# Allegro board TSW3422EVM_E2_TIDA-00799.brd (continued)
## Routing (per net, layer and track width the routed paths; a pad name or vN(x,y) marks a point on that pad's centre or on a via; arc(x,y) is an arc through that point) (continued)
P4.7V:
  vias: v1(33.71,40.51) v1(33.83,42.16) v1(33.83,41.28) v1(34.21,39.88) v1(35.1,39.88) v1(35.74,42.29) v1(35.74,41.28) v1(35.74,40.26) v1(35.74,39.37) v1(36.63,39.62) v1(36.88,40.39)
VIN-: length 7.2
  TOP w0.483: R16.1 R28.1 33.84,90.81 32.91,90.81 U1.2
A_INM: length 16.1
  TOP w0.483: J2.1 3.78,72.98 9.17,67.59 R9.1
A_INP: length 16.1
  TOP w0.483: R4.1 9.23,62.51 3.81,57.1 J1.1
AI_NM: length 4.6
  TOP w0.483: T2.4 T1.6
AI_NP: length 4.6
  TOP w0.483: T2.6 T1.4
AIN+: length 3
  TOP w0.483: C1.1 38.68,62.51 T2.1
AIN-: length 3.1
  TOP w0.483: T2.3 38.66,67.59 C7.1
AINM: length 3.2
  TOP w0.216: U5.8 65.51,64.77 65.57,64.83 67.11,64.83 67.5,64.44 R91.2
AINM_M: length 4.3
  TOP w0.483: R14.1 R10.2 R13.2 L3.1
AINMM_M: length 4.5
  TOP w0.483: R14.2 R11.2 48.82,67.67 49.4,67.09 49.4,65.67 R15.1
AINP: length 3.2
  TOP w0.216: U5.9 65.51,65.27 65.57,65.2 67.51,65.2 R50.2
AINP_P: length 4.3
  TOP w0.483: L1.1 R1.2 R6.1 R2.1
AINPP_P: length 4.3
  TOP w0.483: R3.1 49.43,63.12 48.77,62.46 R5.1 R2.2
B+: length 1.2
  TOP w0.254: R20.1 46.47,75.3 U2.10
B-: length 1.2
  TOP w0.254: U2.11 46.85,75.63 R33.1
B_INM: length 36.7
  TOP w0.483: R42.1 R44.1 R41.1 81,82.71 81,83.25 82.77,85.02 82.77,92.1 J5.1
B_INP: length 36.7
  TOP w0.483: R40.1 R38.1 81.75,80.93 82.29,80.93 84.66,83.3 91.75,83.3 J4.1
BI_NM: length 2.4
  TOP w0.483: R43.2 72.4,72.03 C20.2 72.31,71.64 L7.1
BI_NP: length 2.4
  TOP w0.483: R39.2 71.59,72.84 C20.1 71.2,72.75 L6.1
BIN+: length 7.1
  TOP w0.254: 76.62,75.79 U3.4 76.97,75.07
  TOP w0.483: 76.62,75.79 D2.3 R40.2 ; 76.97,75.07 77.35,74.7 R36.1 77.35,74.36 C101.2
BIN-: length 7.1
  TOP w0.254: 74.63,77.42 U3.6 75.35,77.06
  TOP w0.483: C100.2 R37.1 74.26,77.79 74.63,77.42 ; 75.35,77.06 D6.3 78.19,79.9
BIN_+: length 4.7
  TOP w0.254: 73.93,75.64 U3.9 73.57,76.36
  TOP w0.483: R39.1 73.07,74.78 73.93,75.64 ; C100.1 R37.2 73.2,76.73 73.57,76.36
BIN_-: length 4.8
  TOP w0.254: 75.21,74.36 75.37,74.53 U3.1 75.38,74.55 75.91,74.01
  TOP w0.483: R43.1 74.36,73.51 75.21,74.36 ; 75.91,74.01 76.29,73.64 R36.2 C101.1
BINM: length 3.2
  TOP w0.216: R23.2 67.13,67.87 67.13,67.56 66.69,67.12 66.37,67.12 66.33,67.17 65.23,67.17 65.13,67.27 U5.13
BINP: length 3.2
  TOP w0.216: U5.12 64.96,66.77 65,66.8 66.17,66.8 66.3,66.67 67.13,66.67 67.68,67.23 R26.2
C_INM: length 36.7
  TOP w0.483: J7.1 96.09,71.29 91.08,66.28 87.95,66.28 87.93,66.27 87.82,66.27 R92.1 R54.1 R52.1
C_INP: length 36.7
  TOP w0.483: R51.1 R48.1 87.46,64.11 87.84,63.73 91.2,63.73 96.22,58.72 J6.1
CI_NM: length 2.4
  TOP w0.483: R53.2 74.56,64.44 C25.2 74.22,64.22 L9.1
CI_NP: length 2.4
  TOP w0.483: R49.2 74.56,65.58 C25.1 74.22,65.8 L8.1
CIN+: length 7.1
  TOP w0.254: 80.2,64.11 U4.4 79.95,63.35
  TOP w0.483: C102.2 79.7,61.39 R46.1 79.95,62.82 79.95,63.35 ; R51.2 D3.3 80.2,64.11
CIN-: length 7.1
  TOP w0.254: 79.95,66.66 U4.6 80.2,65.9
  TOP w0.483: 80.2,65.9 D7.3 R52.2 ; 79.95,66.66 79.95,67.19 R47.1 C99.2
CIN_+: length 4.7
  TOP w0.254: 78.19,65.9 U4.9 78.45,66.66
  TOP w0.483: 78.19,65.9 76.98,65.9 R49.1 ; 78.45,66.66 78.45,67.19 R47.2 C99.1
CIN_-: length 4.7
  TOP w0.254: 78.45,63.35 U4.1 78.19,64.11
  TOP w0.483: 78.19,64.11 76.98,64.11 R53.1 ; C102.1 78.69,61.39 R46.2 78.45,62.82 78.45,63.35
CINM: length 6
  TOP w0.254: U5.30 56.35,67.27 56.3,67.22 56.02,67.22 55.55,67.69 54.66,67.69 54.41,67.95 54.41,68.45 54.15,68.71 53.64,68.71 52.94,69.41 R34.2
CINP: length 6
  TOP w0.254: R21.2 52.61,69.16 53.99,67.78 54.49,67.28 55.38,67.28 55.85,66.81 56.3,66.81 56.35,66.77 U5.31
CLK_INP: length 2.2
  TOP w0.483: T3.1 C49.1
CLKINM: length 12.9
  TOP w0.216: U5.22 60.71,69.37 60.78,69.44 60.78,70.33 62.51,72.06 62.51,72.67 62.26,72.92 61.75,72.92 R61.1
  TOP w0.483: 60.99,79.12 60.99,77.24 60.38,76.63 60.38,75.31 60.99,74.7 60.99,73.69 R61.1
CLKINP: length 12.9
  TOP w0.216: U5.21 61.21,69.37 61.14,69.44 61.14,70.17 63.17,72.2 63.17,72.71 63.39,72.92 63.58,72.92 R60.2
  TOP w0.483: 66.07,79.12 66.07,75.41 R60.2
CLOCK_IN: length 8.5
  TOP w0.483: C49.2 J8.1
D_INP: length 9.6
  TOP w0.483: J3.1 JP1.1 R32.2 R22.1
DA0M: length 57
  TOP w0.216: U5.4 65.82,62.77 65.88,62.7 67.08,62.7 70.42,59.36 70.42,52.06 70.18,51.82 70.18,50.33 70.47,50.04 70.47,10.67 70.5,10.64 J12.32
DA0P: length 56.9
  TOP w0.216: U5.3 65.82,62.27 65.88,62.33 66.93,62.33 67.39,61.87 67.39,61.65 67.39,61.44 67.54,61.29 67.76,61.29 67.97,61.29 68.9,60.36 68.9,60.01 69.09,59.82 69.44,59.82 70.05,59.21 70.05,52.21 69.74,51.89 69.74,50.25 70.1,49.89 70.1,10.7 69.99,10.6 J12.34
DA1M: length 57
  TOP w0.216: U5.2 65.82,61.77 65.88,61.7 66.25,61.7 68.2,59.75 68.2,52.51 68.2,52.21 67.51,51.52 67.51,50.29 68.2,49.6 68.2,49.3 68.2,48.35 67.37,47.52 67.37,46.57 68.2,45.74 68.2,44.49 67.37,43.66 67.37,42.71 68.2,41.88 68.2,40.63 67.73,40.16 67.73,38.49 68.2,38.02 68.2,14.78 68.95,14.03 68.95,13.84 68.97,13.83 68.97,10.63 68.99,10.6 J12.38
DA1P: length 57
  TOP w0.216: J12.40 68.49,10.6 68.6,10.7 68.6,13.68 68.59,13.69 68.59,13.87 67.84,14.63 67.84,37.86 67.36,38.34 67.36,40.31 67.83,40.78 67.83,41.73 67.01,42.56 67.01,43.81 67.83,44.64 67.83,45.59 67.01,46.42 67.01,47.67 67.83,48.5 67.83,49.45 67.14,50.14 67.14,51.67 67.83,52.36 67.83,59.6 67.05,60.38 66.83,60.38 66.72,60.27 66.5,60.27 66.35,60.42 66.35,60.64 66.47,60.75 66.47,60.96 66.1,61.33 65.88,61.33 65.82,61.27 U5.1
DAVP: length 4.6
  TOP w0.483: 26.73,95.19 D1.3 R22.2
DB0M: length 56.9
  TOP w0.216: J12.44 67.49,10.67 67.46,10.7 67.46,13.23 66.24,14.45 66.24,29.54 65.34,30.44 65.34,31.39 66.24,32.29 66.24,33.55 65.34,34.45 65.34,35.4 66.24,36.31 66.24,37.56 65.34,38.46 65.34,39.42 66.24,40.32 66.24,41.58 65.34,42.48 65.34,43.43 66.24,44.33 66.24,45.59 65.34,46.49 65.34,47.44 66.24,48.35 66.24,49.6 65.34,50.5 65.34,51.46 66.24,52.36 66.24,56.43 64.14,58.53 64.14,59.59 64.21,59.66 U5.56
DB0P: length 57
  TOP w0.216: J12.46 66.99,10.6 67.1,10.7 67.1,13.08 65.87,14.3 65.87,29.38 64.97,30.29 64.97,31.54 65.87,32.44 65.87,33.4 64.97,34.3 64.97,35.56 65.87,36.46 65.87,37.41 64.97,38.31 64.97,39.57 65.87,40.47 65.87,41.42 64.97,42.33 64.97,43.58 65.87,44.48 65.87,45.44 64.97,46.34 64.97,47.6 65.87,48.5 65.87,49.45 64.97,50.35 64.97,51.61 65.87,52.51 65.87,56.27 63.78,58.37 63.78,59.59 63.71,59.66 U5.55
DB1M: length 56.9
  TOP w0.216: U5.54 63.21,59.66 63.14,59.59 63.14,56.86 64.21,55.79 64.21,52.32 63.27,51.38 63.27,50.43 64.21,49.49 64.21,48.23 63.27,47.29 63.27,46.34 64.21,45.4 64.21,44.14 63.27,43.2 63.27,42.25 64.21,41.31 64.21,40.05 63.27,39.11 63.27,38.16 64.21,37.22 64.21,35.96 63.27,35.02 63.27,34.07 64.21,33.13 64.21,31.87 63.27,30.93 63.27,29.98 64.21,29.04 64.21,14.25 65.96,12.5 65.96,10.7 65.99,10.67 J12.50
DB1P: length 57
  TOP w0.216: J12.52 65.49,10.6 65.6,10.7 65.6,12.34 63.84,14.1 63.84,28.89 62.9,29.83 62.9,31.09 63.84,32.03 63.84,32.98 62.9,33.92 62.9,35.18 63.84,36.12 63.84,37.07 62.9,38.01 62.9,39.27 63.84,40.21 63.84,41.16 62.9,42.1 62.9,43.35 63.84,44.29 63.84,45.25 62.9,46.19 62.9,47.44 63.84,48.38 63.84,49.34 62.9,50.28 62.9,51.53 63.84,52.47 63.84,55.64 62.78,56.71 62.78,59.59 62.71,59.66 U5.53
DBIN+: length 1
  TOP w0.483: L4.1 R20.2
DBIN-: length 1
  TOP w0.483: L5.1 R33.2
DBIN_M: length 3.6
  TOP w0.483: L5.2 51.32,71.86 51.32,71.5 52.04,70.78 R34.1
DBIN_P: length 3.6
  TOP w0.483: L4.2 R25.2 50.24,70.78 C12.1 51.32,70.06 R21.1
DC0M: length 56.9
  TOP w0.216: U5.46 59.21,59.66 59.14,59.59 59.14,57.26 57.75,55.87 57.75,54.54 58.65,53.64 58.65,52.38 57.75,51.48 57.75,50.53 58.65,49.63 58.65,48.37 57.75,47.47 57.75,46.52 58.65,45.62 58.65,44.36 57.75,43.46 57.75,42.5 58.65,41.6 58.65,40.34 57.75,39.44 57.75,38.49 58.65,37.59 58.65,36.33 57.75,35.43 57.75,34.48 58.65,33.58 58.65,32.32 57.75,31.42 57.75,13.64 56,11.89 J12.70
DC0P: length 56.9
  TOP w0.216: J12.72 55.5,11.91 57.38,13.79 57.38,31.57 58.28,32.47 58.28,33.42 57.38,34.32 57.38,35.58 58.28,36.48 58.28,37.44 57.38,38.34 57.38,39.6 58.28,40.5 58.28,41.45 57.38,42.35 57.38,43.61 58.28,44.51 58.28,45.46 57.38,46.36 57.38,47.62 58.28,48.52 58.28,49.48 57.38,50.38 57.38,51.64 58.28,52.54 58.28,53.49 57.38,54.39 57.38,56.02 58.78,57.42 58.78,59.59 58.71,59.66 U5.45
DC1M: length 57
  TOP w0.216: U5.44 58.21,59.66 58.14,59.59 58.14,58.7 56.12,56.68 56.12,54.14 56.85,53.42 56.85,52.16 55.94,51.26 55.94,50.3 56.85,49.4 56.85,48.15 55.94,47.24 55.94,46.29 56.85,45.39 56.85,44.13 55.94,43.23 55.94,42.28 56.85,41.38 56.85,40.12 55.94,39.22 55.94,38.26 56.85,37.36 56.85,36.11 55.94,35.2 55.94,34.25 56.85,33.35 56.85,32.09 55.94,31.19 55.94,14.36 54.4,12.82 54.4,11.81 54.5,11.72 J12.76
DC1P: length 57
  TOP w0.216: U5.43 57.71,59.66 57.78,59.59 57.78,58.86 55.75,56.83 55.75,53.99 56.48,53.26 56.48,52.31 55.58,51.41 55.58,50.15 56.48,49.25 56.48,48.3 55.58,47.4 55.58,46.14 56.48,45.24 56.48,44.28 55.58,43.38 55.58,42.13 56.48,41.22 56.48,40.27 55.58,39.37 55.58,38.11 56.48,37.21 56.48,36.26 55.58,35.36 55.58,34.1 56.48,33.2 56.48,32.25 55.58,31.34 55.58,14.52 54,12.94 J12.78
DCLKM: length 56.9
  TOP w0.216: U5.51 61.71,59.66 61.64,59.59 61.64,54.87 62.52,53.99 62.52,52.32 61.43,51.23 61.43,50.28 62.33,49.38 62.33,48.12 61.43,47.22 61.43,46.27 62.33,45.36 62.33,44.11 61.43,43.2 61.43,42.25 62.33,41.35 62.33,40.09 61.43,39.19 61.43,38.24 62.33,37.34 62.33,36.08 61.43,35.18 61.43,34.23 62.33,33.32 62.33,32.07 61.43,31.16 61.43,30.21 62.33,29.31 62.33,13.63 64.49,11.47 J12.56
DCLKP: length 56.8
  TOP w0.216: J12.58 63.99,11.37 61.96,13.4 61.96,29.16 61.06,30.06 61.06,31.32 61.96,32.22 61.96,33.17 61.06,34.07 61.06,35.33 61.96,36.23 61.96,37.18 61.06,38.09 61.06,39.34 61.96,40.25 61.96,41.2 61.06,42.1 61.06,43.36 61.96,44.26 61.96,45.21 61.06,46.11 61.06,47.37 61.96,48.27 61.96,49.22 61.06,50.13 61.06,51.38 62.15,52.48 62.15,53.84 61.28,54.71 61.28,59.59 61.21,59.66 U5.50
DD0M: length 56.9
  TOP w0.216: U5.42 56.1,61.27 56.04,61.33 55.53,61.33 55.18,60.99 55.18,60.77 55.26,60.69 55.26,60.47 55.11,60.32 54.9,60.32 54.81,60.4 54.6,60.4 53.76,59.56 53.76,54.17 54.64,53.29 54.64,52.03 53.76,51.16 53.76,50.2 54.64,49.33 54.64,48.07 53.99,47.42 53.99,46.01 54.64,45.37 54.64,44.11 53.76,43.23 53.76,14.6 52.9,13.75 52.9,10.55 53.03,10.41 J12.82
DD0P: length 57
  TOP w0.216: U5.41 56.1,61.77 56.04,61.7 55.38,61.7 53.39,59.72 53.39,54.01 54.27,53.14 54.27,52.19 53.39,51.31 53.39,50.05 54.27,49.18 54.27,48.22 53.62,47.58 53.62,45.86 54.27,45.21 54.27,44.26 53.39,43.38 53.39,14.76 52.53,13.9 J12.84
DD1M: length 57
  TOP w0.216: U5.40 56.1,62.27 56.04,62.33 54.8,62.33 54.51,62.04 54.51,61.64 54.33,61.47 53.94,61.47 53.02,60.56 53.02,60.34 53.04,60.32 53.04,60.11 52.89,59.95 52.68,59.95 52.66,59.97 52.44,59.97 51.47,59 51.47,9.58 J12.88
DD1P: length 57.1
  TOP w0.216: J12.90 51.1,9.67 51.1,59.16 54.65,62.7 56.04,62.7 56.1,62.77 U5.39
DIN_P: length 3.2
  TOP w0.483: R89.2 C11.1 U1.3
DINM: length 6.8
  TOP w0.216: U5.35 56.41,64.77 56.35,64.83 50.88,64.83 R3.2
DINP: length 6.8
  TOP w0.216: U5.34 56.41,65.27 56.35,65.2 50.88,65.2 R15.2
FCLKM: length 56.9
  TOP w0.216: J12.64 57.5,10.52 57.4,10.61 57.4,11.25 59.7,13.55 59.7,31.12 60.6,32.02 60.6,33.27 59.7,34.18 59.7,35.13 60.6,36.03 60.6,37.29 59.7,38.19 59.7,39.14 60.6,40.04 60.6,41.3 59.7,42.2 59.7,43.15 60.6,44.06 60.6,45.31 59.7,46.22 59.7,47.17 60.6,48.07 60.6,49.33 59.7,50.23 59.7,51.18 60.6,52.08 60.6,53.34 59.7,54.24 59.7,55.93 60.64,56.87 60.64,59.59 60.71,59.66 U5.49
FCLKP: length 56.9
  TOP w0.216: U5.48 60.21,59.66 60.28,59.59 60.28,57.02 59.33,56.08 59.33,54.09 60.24,53.19 60.24,52.24 59.33,51.33 59.33,50.08 60.24,49.17 60.24,48.22 59.33,47.32 59.33,46.06 60.24,45.16 60.24,44.21 59.33,43.31 59.33,42.05 60.24,41.15 60.24,40.2 59.33,39.29 59.33,38.04 60.24,37.14 60.24,36.18 59.33,35.28 59.33,34.02 60.24,33.12 60.24,32.17 59.33,31.27 59.33,13.7 57,11.37 J12.66
FPGA_CSEL: length 67.1
  TOP w0.203: J12.115 v1(44.5,4.6)
  TOP w0.254: R70.1 v1(102.67,20.96)
  BOTTOM w0.203: v1(102.67,20.96) 91.01,9.3 49.68,9.3 47.04,6.65 47.04,6.07 45.59,4.62 44.53,4.62 v1(44.5,4.6)
FPGA_SCLK: length 62.9
  TOP w0.203: J12.119 43.49,3.93 43.18,4.24 v1(43.18,4.85)
  TOP w0.254: R67.1 v1(95.81,20.96)
  BOTTOM w0.203: v1(95.81,20.96) 87.12,12.27 48.21,12.27 46.79,10.85 46.79,9.4 44.02,6.63 44.02,6.07 43.18,5.23 v1(43.18,4.85)
FPGA_SDI: length 65.9
  TOP w0.203: J12.117 v1(43.99,5.18)
  TOP w0.254: R68.1 v1(100.38,20.96)
  BOTTOM w0.203: v1(43.99,5.18) 45.21,5.18 46,5.97 46,6.83 49.16,9.99 89.42,9.99 v1(100.38,20.96)
FPGA_SDO: length 63.5
  TOP w0.203: J12.113 v1(45.01,5.82)
  TOP w0.254: R69.1 v1(98.09,20.96)
  BOTTOM w0.203: v1(45.01,5.82) 44.91,5.92 44.91,6.76 48.29,10.13 48.29,10.85 49.03,11.59 88.73,11.59 v1(98.09,20.96)
FTDI_VCCIO1.8V: length 92.9
  TOP w0.483: U6.4 v1(100.26,27.29) ; FB6.1 v1(25.07,44.6)
  LYR3_PWR w0.483: v1(100.26,27.29) 100.26,28.58 99.38,29.46 97.08,29.46 89.46,37.08 65.96,37.08 65.58,37.47 62.28,37.47 61.9,37.85 49.94,37.85 48.92,38.86 45.06,38.86 44.88,38.68 42.95,38.68 42.37,38.1 40.26,38.1 38,35.84 36.68,35.84 35.94,36.09 33.86,36.09 33.32,36.63 27.51,36.63 27.05,37.08 27.05,38.58 23.52,42.11 23.52,43.05 v1(25.07,44.6)
IN+: length 9.4
  TOP w0.305: C13.2 43.72,78.76 U2.2
  TOP w0.483: R27.2 C10.1 v1(44.6,83.46) ; v1(43.1,79.75) 43.1,79.69 C13.2
  BOTTOM w0.483: v1(43.1,79.75) 42.54,80.32 42.54,81.31 44.6,83.37 v1(44.6,83.46)
IN-: length 4.2
  TOP w0.305: U2.3 43.42,78.36 C13.1
  TOP w0.483: C8.1 R19.2 42.49,78.86 C13.1
INM: length 3.6
  TOP w0.483: R29.1 42.97,82.01 R27.1 C9.2 R30.2
INP: length 5.3
  TOP w0.483: R19.1 39.84,80.46 R17.1 C9.1 R18.2
N4.7V:
  vias: v1(43.36,27.81) v1(43.48,26.54) v1(43.87,27.43) v1(43.87,24.13) v1(44.37,27.81) v1(44.63,26.54) v1(44.88,25.53) v1(45.14,27.56)
OUT+: length 11.3
  TOP w0.483: R18.1 U1.6 34.01,87.91 34.01,88.81 35.75,90.55 37.9,90.55 R16.2
PDN: length 65.8
  TOP w0.203: U5.37 56.27,63.77 56.26,63.78 55.86,63.78 55.84,63.77 v1(55.18,63.77)
  BOTTOM w0.203: JP2.2 75.25,57.39 75.25,63.11 66.5,71.86 65.71,71.86 65.56,72.01 64.28,72.01 63.83,72.47 63.43,72.47 62.97,72.01 62.41,72.01 60.63,70.23 59.74,70.23 58.85,69.34 57.33,69.34 57.07,69.6 54.91,69.6 54.41,69.09 54.41,64.54 v1(55.18,63.77)
RESET: length 59.6
  TOP w0.203: v1(59.84,70.82) 59.71,70.68 U5.24
  BOTTOM w0.203: 98.45,47.62 85.78,47.62 75.62,57.78 75.62,62.86 75.58,62.9 75.58,63.24 66.63,72.19 66.55,72.19 66.4,72.34 66.4,72.54 66.11,72.82 65.66,72.82 65.58,72.9 64.77,72.9 64.56,73.1 64.16,73.1 63.96,72.9 61.62,72.9 59.84,71.12 v1(59.84,70.82)
  BOTTOM w0.254: SW1.1 98.6,44.25 R58.1 98.58,46.38 C47.1 98.45,47.62
SCLK: length 18.2
  TOP w0.203: R71.1 v1(95.81,23.3)
  BOTTOM w0.254: JP3.2 81.2,25.65 81.2,24.51 83.44,22.28 94.78,22.28 v1(95.81,23.3)
SDATA: length 13.7
  TOP w0.203: R72.1 v1(100.38,23.37)
  BOTTOM w0.203: JP4.2 90.22,24.38 99.75,24.38 100.38,23.75 v1(100.38,23.37)
SDOUT: length 15.8
  TOP w0.254: R69.2 v1(98.09,23.37)
  BOTTOM w0.203: v1(98.09,23.37) 97.97,23.37 97.46,23.88 92.25,23.88 91.36,22.99 87.81,22.99 JP6.2
SEN: length 12.1
  TOP w0.254: R70.2 v1(102.67,23.37)
  BOTTOM w0.203: v1(102.67,23.37) 102.67,23.75 101.4,25.02 93.52,25.02 JP5.2
SYSREF_IN: length 14.7
  BOTTOM w0.483: C53.2 J10.1
SYSREFINP: length 2.3
  BOTTOM w0.483: R63.1 55.04,84.71
SYSREFM: length 12.5
  TOP w0.216: R65.1 56.67,72.92 57.04,72.92 57.47,72.49 57.47,71.79 58.78,70.48 58.78,69.44 58.71,69.37 U5.26
  TOP w0.483: v1(55.5,74.14) 56.06,73.58 R65.1
  BOTTOM w0.483: v1(55.5,74.14) 55.04,74.6 55.04,79.12
SYSREFP: length 12.5
  TOP w0.216: R64.2 58.5,72.92 58.05,72.92 57.84,72.71 57.84,71.95 59.14,70.64 59.14,69.44 59.21,69.37 U5.25
  TOP w0.483: v1(59.59,74.07) 59.11,73.58 R64.2
  BOTTOM w0.483: 60.12,79.12 60.12,74.6 v1(59.59,74.07)
T1_M: length 2.8
  TOP w0.483: R12.1 T1.1
T1_P: length 2.8
  TOP w0.483: R4.2 T1.3
VCM: length 83.7
  TOP w0.254: v1(45.87,64.29) R8.2 C4.2 ; U5.27 58.21,69.7 v1(57.96,69.95)
  BOTTOM w0.203: TP1.1 87.5,50.5 87.5,56.77 87,57.28 76.89,57.28 76,58.17 76,63.25 75.91,63.33 75.91,63.38 74.47,64.81 74.47,69.47
  BOTTOM w0.305: R45.1 68.61,77.57 68.61,74.78 67.36,73.53 ; v1(45.87,64.29) 45.87,71.78 46.86,72.77 54.91,72.77 C48.1 57.73,69.95 v1(57.96,69.95) 61.54,73.53 67.36,73.53 ; 67.36,73.53 67.36,72.64 70.54,69.47 74.47,69.47 R55.1
N18154317: length 52.5
  TOP w0.203: U5.16 63.71,69.63 64.06,69.98 64.59,69.98 v1(64.77,70.15)
  BOTTOM w0.203: JP3.1 80.95,33.4 82.73,35.18 82.73,42.93 71.93,53.72 71.93,62.91 66.07,68.77 66.07,68.91 65.78,69.19 65.65,69.19 64.92,69.92 64.92,70 v1(64.77,70.15)
N18154318: length 56.6
  TOP w0.203: v1(65.13,71.17) 64.68,71.17 63.21,69.7 U5.17
  BOTTOM w0.203: v1(65.13,71.17) 65.3,70.99 65.84,70.99 73,63.83 73,54.6 73.03,54.57 73.03,54.28 88.7,38.61 JP4.1
N18154319: length 55.1
  TOP w0.203: v1(62.23,70) 62.21,69.98 U5.19
  BOTTOM w0.203: v1(62.23,70) 63.5,70 64.16,70.66 64.64,70.66 64.67,70.64 64.97,70.64 65.25,70.35 65.25,70.05 65.79,69.52 65.92,69.52 66.4,69.04 66.4,68.91 72.31,62.99 72.31,54.1 84.89,41.53 JP6.1
N18154320: length 59.6
  TOP w0.203: U5.18 62.71,69.82 64.03,71.15 v1(64.03,71.3)
  BOTTOM w0.203: v1(64.03,71.3) 64.24,71.5 64.77,71.5 64.93,71.65 65.33,71.65 65.48,71.5 65.84,71.5 73.33,64.01 73.33,54.74 92.63,35.43 R56.2 JP5.1
N18158256: length 8
  TOP w0.381: 103.51,34.63 103.51,34.88 103.56,34.92 ; 104.08,36.7 103.56,36.18 103.56,35.99
  TOP w0.483: C59.1 103.56,35.99 C58.1 103.51,34.63 U6.20
  TOP w1.016: 104.08,36.7 104.06,36.72 FB1.1
N18158298: length 3.1
  TOP w0.254: U6.3 99.61,23.11 99.11,22.61
N18158304: length 3.5
  TOP w0.254: R71.2 96.82,23.11 98.31,24.6 U6.1
N18158332: length 17.5
  TOP w0.381: J13.2 110.45,39.54 C61.1
  TOP w0.483: C61.1 109.25,39.37 108.76,38.89 108.76,31.37 107.87,30.48 106.73,30.48 106.11,31.1 U6.16
N18158362: length 2.6
  TOP w0.483: C62.1 105.46,34.68 U6.17
N18158372: length 14.3
  TOP w0.381: C60.1 110.54,40.34 J13.3
  TOP w0.483: U6.15 106.76,33 107.54,33.78 107.54,39.39 108.74,40.59 C60.1
N18158488: length 3.1
  TOP w0.254: R72.2 100.91,23.09 U6.5
N18185709:
  vias: v1(24.18,31.12) v1(24.18,30.1) v1(24.82,30.61) v1(24.82,29.46) v1(24.82,28.58) v1(24.82,26.92) v1(24.94,27.69) v1(25.32,27.05) v1(25.45,28.96) v1(25.58,31.12) v1(25.58,30.1) v1(25.7,28.07) v1(26.09,29.72) v1(26.09,27.56) v1(26.09,26.92) v1(26.21,30.61) v1(26.21,28.96)
N18185817: length 2.8
  TOP w0.203: D4.1 R76.2
N18186847: length 3.4
  TOP w0.254: R75.2 104.81,23.74 U6.11
N18187243: length 5.2
  TOP w0.508: R74.1 111.28,43.28 111.84,42.72 111.84,41.5 112.2,41.14 J13.4
N18187932: length 2.3
  BOTTOM w0.254: SW1.2 105.08,44.27 R57.2
N18195117: length 2.1
  TOP w0.635: R61.2 62.69,73.53 ; 62.69,73.53 R60.1 ; 62.69,73.53 C50.1
N18195272: length 6.5
  TOP w0.508: 63.53,79.12 v1(63.53,81.92) 63.53,84.71
  BOTTOM w0.483: v1(63.53,81.92) C52.1
N18195497: length 2.1
  TOP w0.635: R64.1 57.61,73.53 ; 57.61,73.53 R65.2 ; 57.61,73.53 C54.1
N18195560: length 6.5
  TOP w0.508: v1(57.6,81.92) 56.69,81.92
  BOTTOM w0.483: T4.2 v1(57.6,81.92) T4.5
N18310229: length 6.5
  TOP w0.483: T1.5 v1(22.6,65.05) T1.2
  BOTTOM w0.483: C5.2 22.58,65.03 v1(22.6,65.05)
N18310285: length 4.8
  TOP w0.483: R6.2 44.86,64.62 R8.1 C3.2 R10.1
N18310303: length 2.5
  TOP w0.483: L2.2 47.32,64.55 C2.1 R5.2
N18310305: length 2.5
  TOP w0.483: R11.1 C2.2 47.27,65.56 L2.1
N18310412: length 3.1
  TOP w0.483: L1.2 R1.1 C1.2
N18310438: length 3.1
  TOP w0.483: C7.2 R13.1 L3.2
N18310637: length 6.7
  TOP w0.483: T2.2 v1(32.79,65.05) T2.5
  BOTTOM w0.483: C6.2 32.74,65 v1(32.79,65.05)
N18328495: length 7
  TOP w0.305: U2.4 43.54,77.52 42.88,77.52
  TOP w0.483: R17.2 39.92,78.99 C8.2 39.67,78.53 39.67,77.65 40.21,77.11 40.89,77.11 41.3,77.52 42.88,77.52
N18328553: length 4.3
  TOP w0.305: 44.58,79.04 44.58,78.61 U2.1
  TOP w0.483: 44.58,79.04 44.58,80.22 R29.2 C10.2
N18331866: length 2.6
  TOP w0.381: JP1.2 20.72,105.16 21.26,105.16 R31.1
N18332861: length 3.8
  TOP w0.483: L6.2 C21.1 68.45,70 R24.2 68.36,69.61 R23.1
N18332866: length 3.8
  TOP w0.483: R26.1 69.17,68.8 R24.1 69.56,68.89 C21.2 L7.2
N18333057: length 8
  TOP w0.203: v2(74.14,76.94) 74.4,76.94 74.81,76.52 U3.7
  BOTTOM w0.203: R45.2 71.42,80.62 C22.1 71.7,80.9 72.31,80.9 72.52,80.7 72.52,79.58 72.31,79.38 72.31,78.74 72.49,78.56 72.49,78.54 74.09,76.94 v2(74.14,76.94)
N18344049: length 3.8
  TOP w0.483: R50.1 69.99,65.58 R62.2 70.33,65.8 C26.1 L8.2
N18344053: length 3.8
  TOP w0.483: L9.2 C26.2 70.33,64.22 R62.1 69.99,64.44 R91.1
N18344107: length 8
  TOP w0.203: v2(79.17,66.8) 79.45,66.53 U4.7
  BOTTOM w0.203: v2(79.17,66.8) 79.17,69.09 78.66,69.6 76.63,69.6 R55.2 76.15,70.13 C27.1
N18356381: length 2.2
  TOP w0.305: C80.1 41.76,37.77 U10.6
N18356397: length 4
  TOP w0.305: U10.2 35.17,38.43 34.98,38.23 33.83,38.23 33.83,37.13
N18358821: length 5.7
  TOP w0.381: C91.1 33.32,26.92 33.71,26.54 36.75,26.54 37.13,26.92 37.13,27.67 U11.5
N18358826: length 2.1
  TOP w0.381: U11.3 34.04,30.43 C91.2
N18359253: length 1.3
  TOP w0.305: C89.1 46.98,31.82 U12.6
N18359269: length 1.5
  TOP w0.305: C88.2 46.33,26.36 U12.2
  vias: v1(46.66,25.53) v1(46.66,24.38) v1(47.04,25.02) v1(47.04,23.75)
N18364475: length 28.7
  TOP w0.508: R82.1 38.59,50.86 U13.1 v1(40.06,51.69)
  BOTTOM w0.203: TP4.1 21.64,50.42 28.12,56.9 37.77,56.9 39.8,54.86 39.8,51.94 v1(40.06,51.69)
N18386721: length 3.3
  TOP w0.305: U8.2 v1(25.96,47.62) ; v1(25.96,49.02) 25.96,49.94 L10.2
  BOTTOM w0.305: v1(25.96,47.62) v1(25.96,49.02)
N18386761: length 1.2
  TOP w0.305: C24.2 33.45,46.33 U9.3
N18386804: length 1.6
  TOP w0.305: R81.2 34.32,46.61 34.21,46.61 33.95,46.87 U9.4
N18386812: length 1.4
  TOP w0.279: U9.13 C29.1
N18386907: length 2.4
  TOP w0.305: 28.63,47.62 U8.5
  TOP w0.381: R77.2 R79.1
N18386909: length 2.4
  TOP w0.305: U8.1 26.21,48.13 26.18,48.16 25.74,48.16 25.71,48.13 R80.1 R78.2
N18422421: length 5.2
  TOP w0.254: JP7.2 R41.2
N18422424: length 2.2
  TOP w0.203: JP7.3 C103.1
N18424509: length 5.2
  TOP w0.203: JP8.2 R92.2
N18424511: length 2.2
  TOP w0.203: JP8.3 C104.1

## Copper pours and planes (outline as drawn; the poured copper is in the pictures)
5.0V on TOP: 21.64,19.3 21.64,21.21 22.09,21.65 24.12,21.65 24.31,21.84 24.31,25.27 26.97,25.27 26.97,17.15 20.88,17.15 20.88,18.54
5.0V on LYR3_PWR: 21.64,19.3 21.64,21.21 22.09,21.65 24.12,21.65 24.31,21.84 24.31,25.27 26.59,25.27 26.97,24.89 26.97,17.15 20.88,17.15 20.88,18.54
5.0V_IN on TOP (solid shape): 23.48,22.05 19.67,22.05 19.67,26.57 23.48,26.57
5.0V_IN on TOP: 20.24,17.78 7.8,17.78 7.8,33.66 8.94,33.66 8.94,35.05 22.15,35.05 22.15,29.97 22.02,29.85 20.5,29.85 20.24,29.59
5.0V_IN on BOTTOM: 3.35,22.23 3.35,43.18 14.15,43.18 14.15,34.92 20.5,28.58 20.5,22.23
5.0V_IN on LYR2_GND, LYR5_GND: 17.07,27.94 17.07,22.99 20.24,22.99 20.24,27.94
5.0V_IN on LYR3_PWR: 20.24,26.92 23.93,26.92 24.05,26.8 24.05,21.97 20.24,21.97 20.24,17.78 7.8,17.78 7.8,33.66 8.94,33.66 8.94,35.05 22.15,35.05 22.15,29.97 22.02,29.85 20.5,29.85 20.24,29.59
5VIN on TOP: 39.17,38.86 39.17,40.13 41.96,40.13 41.96,38.86
5VIN on TOP: 27.74,19.18 27.74,21.97 30.91,21.97 30.91,22.61 32.82,22.61 33.71,21.72 33.71,18.92 32.56,18.92 32.31,19.18
5VIN on TOP: 35.86,29.97 35.86,31.88 33.71,31.88 33.71,32.89 39.17,32.89 39.17,37.34 42.09,37.34 42.09,31.88 36.37,31.88 36.37,29.97
5VIN on LYR3_PWR: 27.74,19.18 27.74,21.97 30.91,21.97 30.91,22.61 32.82,22.61 33.96,21.46 33.96,19.18 33.71,18.92 32.44,18.92 32.18,19.18
5VIN on LYR4_PWR: 5.26,17.78 5.26,40.01 22.15,40.01 22.15,47.5 23.14,48.49 30.86,48.49 36.17,43.18 43.87,43.18 43.99,43.05 43.99,40.01 97.97,40.01 97.97,40.64 117.02,40.64 117.02,17.78
+1.2V on TOP: 35.99,47.24 35.99,50.29 37.77,50.29 37.77,47.24
+1.2V on TOP: 45.24,73.48 44.32,72.57 44.32,71.98 43.99,71.65 43.03,71.65 42.75,71.93 42.75,72.75 43.31,73.3 43.59,73.3 44.5,74.22
+1.2V on LYR3_PWR: 35.99,52.17 35.99,57.12 38.58,59.72 38.58,73.51 38.61,73.53 46.13,73.53 46.13,58.65 37.77,50.29 37.77,47.29 34.87,47.29 34.87,51.05
+1.8V on TOP: 30.91,43.61 29.21,43.61 29.21,45.59 30.91,45.59 30.91,48.64 32.44,48.64 32.44,48.01 33.07,48.01 33.07,46.99 32.44,46.99 32.44,43.94 34.47,43.94 34.47,45.47 35.86,45.47 35.86,46.74 35.99,46.86 39.29,46.86 39.29,48.51 38.15,48.51 38.15,49.28 40.82,49.28 40.94,49.15 40.94,43.61 38.05,43.61 37.24,42.8 30.91,42.8
+1.8V on LYR3_PWR: 30.91,48.64 32.44,48.64 32.44,48.01 33.07,48.01 33.07,46.99 33.32,46.74 38.33,46.74 38.33,49.28 40.82,49.28 40.94,49.15 40.94,42.8 30.91,42.8
+2.1V on TOP, LYR3_PWR: 27.61,52.96 27.61,50.29 27.1,49.78 27.1,48.13 27.61,48.13 28.24,48.77 29.51,48.77 29.51,49.53 31.67,49.53 33.07,50.93 33.07,51.05 32.82,51.31 32.82,52.83 32.69,52.96
+4.7V on TOP: 26.75,42.67 26.75,39.22 26.47,38.94 26.47,37.08 26.72,36.83 32.94,36.83 33.2,37.08 33.2,40.13 33.07,40.26 32.94,40.26 32.94,42.67
+4.7V on TOP: 45.16,75.49 44.35,74.68 44.02,74.68 43.28,73.94 42.37,74.85 41.55,74.85 41.2,75.21 41.2,76 41.53,76.33 42.6,76.33 42.77,76.15 43.28,76.15 43.89,76.76
+4.7V on BOTTOM: 78.66,63.63 78.66,64.77 77.39,64.77 77.39,65.28 78.66,65.28 78.66,65.79 79.43,65.79 79.43,63.63
+4.7V on BOTTOM: 75.8,74.35 74.99,75.15 74.09,74.26 73.73,74.62 74.63,75.51 74.27,75.87 74.81,76.41 76.34,74.89
+4.7V on LYR3_PWR: 73.96,74.17 73.33,73.53 73.58,73.28 73.46,73.15 72.95,73.66 73.71,74.42 73.71,74.68 79.04,80.01 79.17,80.01 79.55,79.63 79.55,79.5 74.22,74.17
+4.7V on LYR3_PWR: 27.74,37.08 27.74,38.61 23.55,42.8 23.55,59.18 30.53,66.17 30.53,79.76 32.94,82.17 45.26,82.17 45.26,85.34 37.9,85.34 37.9,98.55 25.7,98.55 25.7,101.22 41.71,101.22 41.71,90.68 70.28,90.68 71.81,92.2 71.81,95.76 91.74,95.76 92,95.5 92,58.29 84.63,58.29 84.63,61.09 80.31,61.09 80.31,63.63 84.63,63.63 84.63,64.64 77.27,64.64 77.27,64.8 76.38,64.8 76.38,63.63 77.9,63.63 77.9,63.63 78.54,63.63 78.03,63.63 78.03,62.74 73.58,62.74 73.2,63.12 73.2,73.66 73.3,73.66 74.22,72.75 74.24,72.75 75.39,73.89 75.43,73.89 75.58,73.73 75.58,73.72 77.27,72.03 77.29,72.03 78.92,73.66 77.08,75.5 80.06,78.49 80.06,78.61 78.16,80.52 75.49,77.85 75.36,77.85 73.2,80.01 73.2,80.65 76.76,84.2 76.76,85.6 76.12,86.23 74.73,86.23 73.08,84.58 50.52,84.58 50.52,75.34 49.61,74.42 37.26,74.42 37.11,74.27 37.11,59.79 33.48,56.16 29.92,56.16 27.1,53.34 27.1,51.44 29.13,51.44 30.02,50.55 30.02,45.72 32.94,42.8 32.94,37.08 ; 2 cut-outs
-4.7V on TOP: 29.82,90.91 25.37,86.46 28.26,83.57 32.71,88.02
-4.7V on TOP: 36.37,21.46 41.45,21.46 41.45,25.53 40.03,25.53 40.03,25.88 39.95,25.96 36.6,25.96 36.07,25.43 36.07,21.77
-4.7V on LYR3_PWR: 34.85,21.08 31.55,24.38 28.5,24.38 26.97,25.91 26.97,31.62 22.66,31.62 22.66,35.94 14.66,35.94 14.27,36.32 14.27,65.15 25.58,76.45 25.58,97.64 26.8,97.64 26.82,97.66 27.03,97.66 27.03,98.43 27.91,98.43 28.04,98.3 29.13,98.3 29.13,93.34 32.69,89.79 32.69,87.25 29.83,84.39 29.83,66.99 23.04,60.2 23.04,41.91 26.72,38.23 26.72,37.47 27.99,36.2 32.69,36.2 34.85,34.04 34.85,30.23 35.67,29.4 41.77,29.4 42.6,28.58 42.6,24 41.45,22.86 41.45,21.46 39.17,21.46 39.17,21.08
-5V on TOP, LYR3_PWR: 36.75,31.24 36.75,29.85 45.9,29.85 45.9,31.24
A1.8V on TOP, LYR3_PWR: 41.58,46.61 41.58,49.28 43.1,49.28 43.1,52.32 45.14,52.32 45.77,51.69 45.77,46.86 45.52,46.61
AVDD1.8V on TOP: 46.53,48.89 46.53,46.86 45.77,46.1 45.01,46.1 44.63,45.72 44.63,42.29 49.2,42.29 49.45,42.55 49.45,48.89
AVDD1.8V on LYR3_PWR: 44.5,47.62 45.01,48.13 45.01,49.78 46.28,49.78 46.28,53.34 48.31,53.34 48.31,70.36 48.44,70.48 67.23,70.48 67.23,63.12 65.2,63.12 65.2,63.88 55.3,63.88 55.3,64.01 52.25,64.01 52.25,49.78 52.37,49.78 52.37,43.43 50.5,41.55 44.91,41.55 44.15,42.32 44.15,45.01 44.5,45.36
AVDD1.8V on LYR4_PWR: 35.99,65.41 35.99,74.8 69.39,74.8 69.39,63.37 66.47,63.37 66.09,63.75 54.53,63.75 45.52,54.74 45.52,49.28 53.64,49.28 53.64,43.56 53.52,43.43 50.27,43.43 48.74,41.91 45.24,41.91 44.5,42.65 44.5,43.38 44.2,43.69 36.37,43.69 29.01,51.05 29.01,58.42
DVDD1.8V on LYR3_PWR: 55.3,62.99 55.8,63.5 56.69,63.5 56.95,63.25 64.19,63.25 64.31,63.37 66.09,63.37 66.09,63.25 66.47,62.86 71.55,62.86 71.55,60.07 78.66,52.96 105.84,52.96 105.84,40.26 57.33,40.26 55.3,42.29
DVDD1.8V on LYR4_PWR: 45.9,52.7 45.9,54.36 54.79,63.25 54.79,63.63 65.46,63.63 66.22,62.86 66.22,62.36 66.73,61.85 66.73,56.64 66.6,56.52 56.69,56.52 56.69,52.7
GND on TOP (solid shape): 61.6,84.55 62.59,83.56 62.59,82.62 61.88,82.62 61.88,83.25 61.63,83.51 60.38,83.51 60.38,85.26 61.6,85.26
GND on TOP (solid shape): 37.97,38.98 38.34,38.98 38.34,40 38.62,40 38.62,38.98 38.9,38.98 38.9,37.22 38.62,37.22 38.62,36.2 38.34,36.2 38.34,37.22 37.97,37.22 37.97,36.2 37.69,36.2 37.69,37.22 37.4,37.22 37.4,38.98 37.69,38.98 37.69,40 37.97,40
GND on TOP (solid shape): 47.53,29.55 48.56,29.55 48.56,29.27 47.53,29.27 47.53,28.9 48.56,28.9 48.56,28.62 47.53,28.62 47.53,28.33 45.78,28.33 45.78,28.62 44.76,28.62 44.76,28.9 45.78,28.9 45.78,29.27 44.76,29.27 44.76,29.55 45.78,29.55 45.78,29.83 47.53,29.83
GND on BOTTOM (solid shape): 60.75,83.51 59.51,83.51 59.25,83.25 59.25,82.62 58.54,82.62 58.54,83.56 59.53,84.55 59.53,85.26 60.75,85.26
GND on TOP: 23.24,0.38 23.24,13.08 0.38,13.08 0.38,95.83 21.01,116.46 94.56,116.46 121.54,89.48 121.54,13.08 98.68,13.08 98.68,0.38 ; 11 cut-outs
GND on BOTTOM: 23.24,0.38 23.24,13.08 0.38,13.08 0.38,95.83 21.01,116.46 94.56,116.46 121.54,89.48 121.54,13.08 98.68,13.08 98.68,0.38 ; 6 cut-outs
GND on BOTTOM: 76.65,76.03 77.47,75.2 77.89,75.61 77.06,76.44
GND on LYR2_GND, LYR5_GND: 23.24,0.38 23.24,13.08 0.38,13.08 0.38,95.83 21.01,116.46 94.56,116.46 121.54,89.48 121.54,13.08 98.68,13.08 98.68,0.38 ; 3 cut-outs
GND on LYR4_PWR: 23.24,0.38 23.24,13.08 0.38,13.08 0.38,95.83 21.01,116.46 94.56,116.46 121.54,89.48 121.54,13.08 98.68,13.08 98.68,0.38 ; 6 cut-outs
P4.7V on TOP: 33.45,40.26 33.45,42.55 36.78,42.55 36.98,42.34 37.52,42.34 37.52,38.99 33.58,38.99 33.58,40.13
P4.7V on LYR3_PWR: 33.45,38.99 33.45,42.55 37.52,42.55 37.52,38.99
AI_NM on TOP (solid shape): 26.19,67.92 26.19,66.96 25.42,66.96 25.17,66.71 24.46,65.99 23.52,65.99 23.52,66.71 24.15,66.71 24.41,66.96 24.41,68.2 26.19,68.2
AI_NM on TOP (solid shape): 30.96,68.2 31.27,68.2 31.27,66.96 31.52,66.71 32.16,66.71 32.16,65.99 32.03,65.99 31.22,65.99 30.25,66.96 29.49,66.96 29.49,68.23 30.94,68.23
AI_NP on TOP (solid shape): 32.16,64.11 32.16,63.4 31.52,63.4 31.27,63.15 31.27,61.9 29.49,61.9 29.49,62.18 29.49,63.15 30.25,63.15 31.22,64.11
AI_NP on TOP (solid shape): 25.17,63.4 25.42,63.15 26.19,63.15 26.19,61.88 24.74,61.88 24.71,61.9 24.41,61.9 24.41,63.15 24.15,63.4 23.65,63.4 23.52,63.4 23.52,64.11 24.46,64.11
AIN+ on TOP (solid shape): 34.62,64.11 35.33,63.4 35.61,63.12 36.3,63.12 36.32,63.1 36.32,61.9 34.57,61.9 34.57,62.26 34.57,63.15 34.31,63.4 33.68,63.4 33.68,64.11
AIN- on TOP (solid shape): 36.32,66.98 35.61,66.98 34.62,65.99 33.68,65.99 33.68,66.71 34.31,66.71 34.57,66.96 34.57,68.2 36.32,68.2
CLK_INP on TOP (solid shape): 66.68,83.51 65.44,83.51 65.18,83.25 65.18,82.62 64.47,82.62 64.47,83.56 65.18,84.27 65.46,84.55 65.46,85.24 65.49,85.26 66.68,85.26
CLKINM on TOP (solid shape): 62.59,80.97 62.59,80.16 61.63,79.19 61.63,78.45 61.63,78.43 60.36,78.43 60.36,79.88 60.38,79.9 60.38,80.21 61.63,80.21 61.88,80.46 61.88,80.97 61.88,81.1 62.59,81.1
CLKINP on TOP (solid shape): 65.18,80.46 65.44,80.21 66.68,80.21 66.68,78.43 65.44,78.43 65.44,79.19 64.47,80.16 64.47,81.1 65.18,81.1
N4.7V on TOP, LYR3_PWR: 43.1,21.84 43.1,28.07 45.77,28.07 45.77,24.64 44.63,24.64 44.63,21.84
SYSREFINP on BOTTOM (solid shape): 55.67,85.24 55.67,84.55 55.95,84.27 56.66,83.56 56.66,82.62 55.95,82.62 55.95,83.25 55.7,83.51 54.45,83.51 54.45,85.26 55.65,85.26
SYSREFM on BOTTOM (solid shape): 56.66,80.16 55.7,79.19 55.7,78.43 54.45,78.43 54.45,80.21 55.7,80.21 55.95,80.46 55.95,81.1 56.66,81.1
SYSREFP on BOTTOM (solid shape): 59.25,80.97 59.25,80.46 59.51,80.21 60.75,80.21 60.75,79.9 60.78,79.88 60.78,78.43 59.51,78.43 59.51,78.45 59.51,79.19 58.54,80.16 58.54,80.97 58.54,81.1 59.25,81.1
T1_M on TOP (solid shape): 21.11,67.85 21.11,66.96 21.36,66.71 22,66.71 22,65.99 21.06,65.99 20.34,66.71 20.06,66.98 19.38,66.98 19.35,67.01 19.35,68.2 21.11,68.2
T1_P on TOP (solid shape): 22,63.4 21.36,63.4 21.11,63.15 21.11,61.9 19.35,61.9 19.35,63.12 20.06,63.12 21.06,64.11 22,64.11
N18185709 on TOP, LYR3_PWR: 24.56,25.91 24.56,29.85 23.16,29.85 23.16,31.37 26.47,31.37 26.47,25.91
N18195272 on TOP (solid shape): 63.91,80.46 63.91,80.21 64.17,79.95 64.17,79.78 63.91,79.78 63.91,78.43 63.15,78.43 63.15,79.78 62.9,79.78 62.9,79.95 63.15,80.21 63.15,81.1 63.91,81.1
N18195272 on TOP (solid shape): 63.91,84.8 64.17,84.8 64.17,83.76 63.91,83.51 63.91,83.25 63.91,82.62 63.15,82.62 63.15,83.51 62.9,83.76 62.9,83.79 62.9,84.68 62.92,84.7 63.15,84.7 63.15,85.29 63.91,85.29
N18195560 on BOTTOM (solid shape): 57.98,80.21 58.24,79.95 58.24,79.78 57.98,79.78 57.98,78.43 57.22,78.43 57.22,79.78 56.97,79.78 56.97,79.95 57.22,80.21 57.22,80.46 57.22,81.1 57.98,81.1
N18195560 on BOTTOM (solid shape): 57.98,84.7 58.21,84.7 58.24,84.68 58.24,83.79 58.24,83.76 57.98,83.51 57.98,82.62 57.22,82.62 57.22,83.25 57.22,83.51 56.97,83.76 56.97,84.8 57.22,84.8 57.22,85.29 57.98,85.29
N18310229 on TOP (solid shape): 24.84,65.44 26.19,65.44 26.19,64.67 24.84,64.67 24.84,64.42 24.66,64.42 24.41,64.67 23.52,64.67 23.52,65.44 24.41,65.44 24.66,65.69 24.84,65.69
N18310229 on TOP (solid shape): 21.11,65.44 22,65.44 22,64.67 21.36,64.67 21.11,64.67 20.85,64.42 20.83,64.42 19.94,64.42 19.91,64.44 19.91,64.67 19.33,64.67 19.33,65.44 19.81,65.44 19.81,65.69 20.85,65.69
N18310637 on TOP (solid shape): 31.27,65.44 32.16,65.44 32.16,64.67 31.27,64.67 31.01,64.42 30.83,64.42 30.83,64.67 29.49,64.67 29.49,65.44 30.83,65.44 30.83,65.69 31.01,65.69
N18310637 on TOP (solid shape): 34.85,65.69 35.74,65.69 35.76,65.66 35.76,65.44 36.35,65.44 36.35,64.67 35.86,64.67 35.86,64.42 34.82,64.42 34.57,64.67 34.31,64.67 33.68,64.67 33.68,65.44 34.57,65.44 34.82,65.69
N18359269 on TOP, LYR3_PWR: 46.15,26.92 46.15,23.37 47.17,23.37 47.42,23.62 47.42,26.67 47.17,26.92

Small or netless copper shapes (teardrops, artwork), in the pictures only: 1 on BOTTOM

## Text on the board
BOTTOM: BOTTOM SIDE  S06
Board Geometry/Soldermask Bottom: SOLDERMASK BOTTOM
Ref Des/Silkscreen Bottom: SILKSCREEN BOTTOM | GND
User.Comments: 2 | 1 | 60 | 59 | ON | K | 120 | 119 | 62 | 61 | * | 7 | 6 | 12 | DDR2 STD | 1.8V | 3 | 4 | TEXAS INSTRUMENTS | TSW1400 REV D | TSW3422EVM REV E2  TIDA-00799 | ASSEMBLY TOP | ASSEMBLY BOTTOM
TOP: TOP SIDE  S01
Board Geometry/Soldermask Top: SOLDERMASK TOP
Ref Des/Silkscreen Top: SILKSCREEN TOP | MASTER | DUT | HI | LO | TSW3422EVM - HSP003 REV E2 | DINP | DINM | CINP | BINM | BINP | AINM | AINP
LYR2_GND: LAYER 2 - GND   S02
LYR3_PWR: POWER PLANE 1  S03
LYR4_PWR: POWER PLANE 2   S04
LYR5_GND: GROUND PLANE 2  S05
DIMENSION: 0 | TOP SIDE SHOWN
DISPLAY_TOP: PASTEMASK TOP
PLACE_BOUND_TOP: PASTEMASK BOTTOM
User.10: 12/12/15 | U2 FOOTPRINT + CIRCUIT MOVE | 4-13-16 | LIBRA | TIDA-00799
User.11: JV SMITH | N GILL | 12/11/15 | 2.  FINISHED ASSEMBLY MUST BE LEAD FREE AND RoHS COMPLIANT. | 3.  USE WATER SOLUBLE FLUX DURING BOARD ASSEMBLY. | TIDA-00799
User.22: FIGURE | SIZE | 8.0 | 10.0 | 12.0 | 38.0 | 40.0 | 55.0 | 62.0 | 67.0 | 68.0 | 120.0 | 125.0 | 140.0 | 39.0 | DRILL CHART: TOP to BOTTOM | ALL UNITS ARE IN MILS | PLATED | NON-PLATED | QTY | 41 | 2024 | 33 | 273 | 6 | 10 | 3 | 2 | 8 | 4 | 1
User.28: T4 | R57 | C47 | R58 | R56 | C95 | R55 | C27 | C96 | C97 | C94 | C22 | C37 | R45 | C41 | C52 | C38 | C40 | C53 | C48 | C33 | C32 | C31 | C30 | C39 | C46 | R63 | C6 | C5 | D5 | C19 | C18 | C42 | C43 | C36 | C44 | C35 | C34 | C45
